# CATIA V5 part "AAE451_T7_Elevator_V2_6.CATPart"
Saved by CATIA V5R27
Part number: Elevator
Bounding box of the stored display mesh (mm): x 0 to 69.698, y -12.436 to 0.05, z -344.945 to 0
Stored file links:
  W:\AAE 451\AAE451_T7_TailAssembly_V2\AAE451_T7_Elevator_V2_6.CATPart
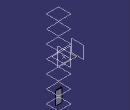
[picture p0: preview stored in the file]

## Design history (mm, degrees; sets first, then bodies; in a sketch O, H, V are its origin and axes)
Set1 "GeometryFromExcel"
  Point1: (1, 0.001, 0)
  Point2: (0.95, 0.0067, 0)
  Point3: (0.9, 0.0121, 0)
  Point4: (0.8, 0.0219, 0)
  Point5: (0.7, 0.0305, 0)
  Point6: (0.6, 0.038, 0)
  Point7: (0.5, 0.0441, 0)
  Point8: (0.4, 0.0484, 0)
  Point9: (0.3, 0.05, 0)
  Point10: (0.25, 0.0495, 0)
  Point11: (0.2, 0.0478, 0)
  Point12: (0.15, 0.0445, 0)
  Point13: (0.1, 0.039, 0)
  Point14: (0.075, 0.035, 0)
  Point15: (0.05, 0.0296, 0)
  Point16: (0.025, 0.0218, 0)
  Point17: (0.0125, 0.0158, 0)
  Point18: (0, 0, 0)
  Point19: (0.0125, -0.0158, 0)
  Point20: (0.025, -0.0218, 0)
  Point21: (0.05, -0.0296, 0)
  Point22: (0.075, -0.035, 0)
  Point23: (0.1, -0.039, 0)
  Point24: (0.15, -0.0445, 0)
  Point25: (0.2, -0.0478, 0)
  Point26: (0.25, -0.0495, 0)
  Point27: (0.3, -0.05, 0)
  Point28: (0.4, -0.0484, 0)
  Point29: (0.5, -0.0441, 0)
  Point30: (0.6, -0.038, 0)
  Point31: (0.7, -0.0305, 0)
  Point32: (0.8, -0.0219, 0)
  Point33: (0.9, -0.0121, 0)
  Point34: (0.95, -0.0067, 0)
  Point35: (1, -0.001, 0)
  Point36: (1, 0.001, 0)
  Point37: (0.95, 0.0067, 0)
  Point38: (0.9, 0.0121, 0)
  Point39: (0.8, 0.0219, 0)
  Point40: (0.7, 0.0305, 0)
  Point41: (0.6, 0.038, 0)
  Point42: (0.5, 0.0441, 0)
  Point43: (0.4, 0.0484, 0)
  Point44: (0.3, 0.05, 0)
  Point45: (0.25, 0.0495, 0)
  Point46: (0.2, 0.0478, 0)
  Point47: (0.15, 0.0445, 0)
  Point48: (0.1, 0.039, 0)
  Point49: (0.075, 0.035, 0)
  Point50: (0.05, 0.0296, 0)
  Point51: (0.025, 0.0218, 0)
  Point52: (0.0125, 0.0158, 0)
  Point53: (0, 0, 0)
  Point54: (0.0125, -0.0158, 0)
  Point55: (0.025, -0.0218, 0)
  Point56: (0.05, -0.0296, 0)
  Point57: (0.075, -0.035, 0)
  Point58: (0.1, -0.039, 0)
  Point59: (0.15, -0.0445, 0)
  Point60: (0.2, -0.0478, 0)
  Point61: (0.25, -0.0495, 0)
  Point62: (0.3, -0.05, 0)
  Point63: (0.4, -0.0484, 0)
  Point64: (0.5, -0.0441, 0)
  Point65: (0.6, -0.038, 0)
  Point66: (0.7, -0.0305, 0)
  Point67: (0.8, -0.0219, 0)
  Point68: (0.9, -0.0121, 0)
  Point69: (0.95, -0.0067, 0)
  Point70: (1, -0.001, 0)
  Curve1: Elements (Point36; Point37; Point38; Point39; Point40; Point41; Point42; Point43; Point44; Point45; Point46; Point47; Point48; Point49; Point50; Point51; Point52; Point53; Point54; Point55; Point56; Point57; Point58; Point59; Point60; Point61; Point62; Point63; Point64; Point65; Point66; Point67; Point68; Point69; Point70)
  Sketch1 on xy-plane, origin (0, 0, 0), H (1, 0, 0), V (0, 1, 0)
    projected curve E1 from edge of Curve1
    point P1 (1, 0.0011)
    line L1 (1, 0.0011) -> (1, -0.001)
    point P3 (1, 0.001)
    point P4 (1, -0.001)
    reference projected point E2 (1, 0.001) from Point1
    reference projected point E3 (1, -0.001) from Point35
    coincidence: P3 E2, P4 E3, P1 P3
Body1 (main body)
  Pad1: profile Sketch1, direction (0, 0, 1), length 1.5215, mirrored extent
  Scaling1: Reference Point40, Ratio 230, ToTransfor Pad1
  Plane1: type Offset, RefPlane yz-plane, Offset 120, reversed
  Sketch2 on xy-plane, origin (0, 0, 0), H (1, 0, 0), V (0, 1, 0)
    reference projected line E1 (69.6979, -7.2245) -> (69.698, -6.7499) from edge [face of Pad1 from Sketch1.L1 | end face of Pad1]
    line L1 (13.6994, -1.0636) -> (13.6965, -12.9194)
    projected curve E2 from edge [face of Pad1 from Sketch1.E1 | end face of Pad1]
    projected curve E3 from edge [face of Pad1 from Sketch1.E1 | end face of Pad1]
    distance E1 L1 = 56
  Pocket1: profile Sketch2, direction (0, 0, -1), through (limit type 3), opposite side through (limit type 3)
  Fillet1: radius 5, on edge [face of Pad1 from Sketch1.E1 | face of Pocket1 from Sketch2.L1]; edge [face of Pocket1 from Sketch2.L1 | face of Pad1 from Sketch1.E1]
  Sketch3 on zx-plane, origin (0, 0, 0), H (-1, 0, 0), V (0, 0, 1)
    line L1 (-135.4649, -344.945) -> (50.2623, -344.945)
    line L2 (50.2623, -344.945) -> (50.2623, -349.945)
    line L3 (50.2623, -349.945) -> (-135.4649, -349.945)
    line L4 (-135.4649, -349.945) -> (-135.4649, -344.945)
    line L5 (-146.4826, 349.945) -> (56.5582, 349.945)
    line L6 (56.5582, 349.945) -> (56.5582, 344.945)
    line L7 (56.5582, 344.945) -> (-146.4826, 344.945)
    line L8 (-146.4826, 344.945) -> (-146.4826, 349.945)
    reference projected line E1 (-69.7, 349.945) -> (160.3, 349.945) from edge [face of Pad1 from Sketch1.E1 | end face of Pad1]
    reference projected line E2 (-69.7, -349.945) -> (160.3, -349.945) from edge [start face of Pad1 | face of Pad1 from Sketch1.E1]
    distance L7 L5 = 5
    horizontal: L1 H, L3 H, L5 H, L7 H
    vertical: L2 V, L4 V, L6 V, L8 V
    coincidence: L5 E1, L3 E2
    symmetry: L7 L1 H
  Pocket2: profile Sketch3, direction (0, -1, 0), through (limit type 3)
  Sketch4 on face of Pocket1 from Sketch2.L1, origin (13.6996, -0.0033, 0), H (-0.0002, -1, 0), V (0, 0, 1)
    line L1 (6.4867, 8) -> (7.4867, 8)
    line L2 (7.4867, 8) -> (7.4867, -8)
    line L3 (7.4867, -8) -> (6.4867, -8)
    line L4 (6.4867, -8) -> (6.4867, 8)
    construction line L5 (6.9867, 7.1913) -> (6.9867, -6.7162)
    reference projected line E1 (1.5418, 344.945) -> (1.5418, -344.945) from edge [face of Pad1 from Sketch1.E1 | face of Fillet1]
    reference projected line E2 (12.4317, 344.945) -> (12.4317, -344.945) from edge [face of Fillet1 | face of Pad1 from Sketch1.E1]
    distance L4 L2 = 1
    distance L1 L3 = 16
    horizontal: L1 H, L3 H
    vertical: L2 V, L4 V
    symmetry: L3 L1 H, L4 L2 L5, E1 E2 L5
  Pocket3: profile Sketch4, direction (1, -0.0002, 0), length 13.7
  RectPattern1: of Pocket3, direction 1 instances 2, spacing 230, along zx-plane
  Mirror1: of RectPattern1, about xy-plane
  Plane2: type Offset, RefPlane face of Pocket2 from Sketch3.L7, Offset 0, reversed
  Plane3: type Offset, RefPlane face of Pocket2 from Sketch3.L1, Offset 0, reversed
  Plane4: type Offset, RefPlane Plane3, Offset 114.98
  Plane5: type Offset, RefPlane Plane4, Offset 114.98
  Plane6: type Offset, RefPlane Plane5, Offset 114.98
  Plane7: type Offset, RefPlane Plane6, Offset 114.98
  Plane8: type Offset, RefPlane Plane7, Offset 114.98
  Split1: SplitPlane Plane4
